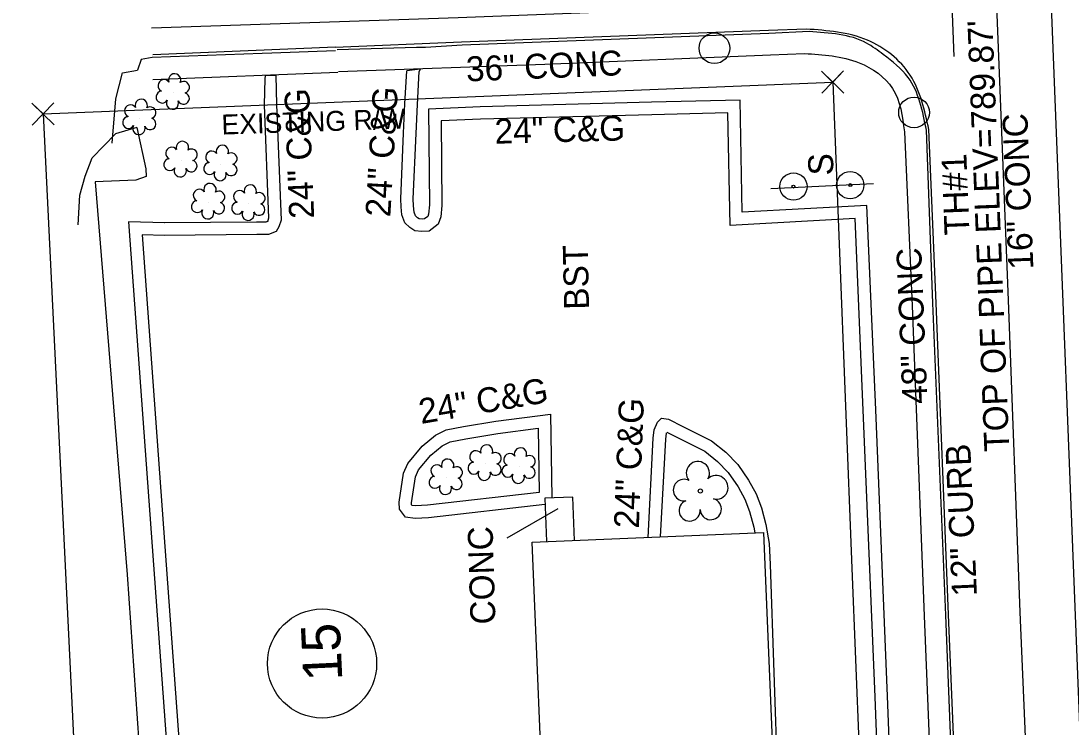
# Model space of a CAD drawing. Extents: x 1627482 to 1629573, y 760826 to 766301.
# Drawn here: x 1628266.8 to 1628435.1, y 762601.5 to 762714.8 of the extents above; entities that cross this region are included whole.
import ezdxf

# ---------------------------------------------------------------- set-up
doc = ezdxf.new("R2010")
doc.units = 0
for name, color, linetype in [('Default', 7, 'Continuous'), ('Exist Building', 7, 'Continuous'), ('Exist Horizontal Alignment', 7, 'Continuous'), ('Exist Other Culture Area Outline', 7, 'Continuous'), ('Exist Other Culture Area Outline Leader', 7, 'Continuous'), ('Exist Other Culture Area Outline Text', 7, 'Continuous'), ('Exist Other Culture Sign CELL', 7, 'Continuous'), ('Exist Other Culture Sign Post Text', 7, 'Continuous'), ('Exist Property Corner CELL', 7, 'Continuous'), ('Exist Property Line', 7, 'Continuous'), ('Exist Property Owner Number CELL', 7, 'Continuous'), ('Exist Right of Way Line', 7, 'Continuous'), ('Exist Right of Way Line Text', 7, 'Continuous'), ('Exist Roads Curbs', 7, 'Continuous'), ('Exist Roads Curbs Text', 7, 'Continuous'), ('Exist Roads EOP', 7, 'Continuous'), ('Exist Roads EOP Other', 7, 'Continuous'), ('Exist Roads EOP Other Text', 7, 'Continuous'), ('Exist Roads EOT', 7, 'Continuous'), ('Exist Utilities Other Pole CELL', 7, 'Continuous'), ('Exist Utilities Water Test Hole SUE LOS A Leader', 7, 'Continuous'), ('Exist Utilities Water Test Hole SUE LOS A Text', 7, 'Continuous'), ('Exist Vegetation Shrub CELL', 7, 'Continuous'), ('Exist Vegetation Tree CELL', 7, 'Continuous'), ('Exist Vegetation Woods Line', 7, 'Continuous')]:
    doc.layers.add(name, color=color, linetype=linetype)

# ---------------------------------------------------------------- blocks, each defined once
blk = doc.blocks.new('POINT_DISPLAY')
at = {"layer": 'Default'}
blk.add_line((0, 0), (0, 0), dxfattribs=at)
blk = doc.blocks.new('EXIST PROPERTY CORNER')
at = {"layer": 'Exist Property Corner CELL'}
blk.add_lwpolyline([(-3.81, 0), (3.81, 0), (0, 0), (0, 3.81), (0, -3.81)], dxfattribs=at)
blk.add_blockref('POINT_DISPLAY', (0, 0), dxfattribs=at)

msp = doc.modelspace()

# ---------------------------------------------------------------- linework, layer by layer
at = {"layer": 'Exist Building'}
msp.add_lwpolyline([(1628350.78, 762581.05), (1628348.7, 762631.18), (1628385.79, 762632.71), (1628387.44, 762592.91), (1628392, 762593.1), (1628392.29, 762586.01), (1628387.82, 762585.82), (1628387.93, 762582.98), (1628385.47, 762582.88), (1628386.67, 762554.01), (1628391.58, 762554.21), (1628391.79, 762548.97), (1628386.95, 762548.77), (1628387, 762547.42), (1628357.87, 762546.21), (1628356.42, 762581.29)], close=True, dxfattribs=at)
at = {"layer": 'Exist Horizontal Alignment'}
msp.add_line((1628461.18, 761975.88), (1628351.56, 764755.6), dxfattribs=at)
at = {"layer": 'Exist Other Culture Area Outline'}
msp.add_lwpolyline([(1628355.52, 762631.46), (1628355.24, 762638.41), (1628350.72, 762638.23), (1628350.99, 762631.27)], dxfattribs=at)
at = {"layer": 'Exist Other Culture Area Outline Leader'}
msp.add_line((1628352.81, 762636.51), (1628344.66, 762631.8), dxfattribs=at)
at = {"layer": 'Exist Other Culture Sign CELL'}
msp.add_line((1628403.45, 762688.65), (1628386.99, 762687.86), dxfattribs=at)
for centre, radius in [((1628390.59, 762688.21), 2.18), ((1628399.7, 762688.44), 2.18), ((1628390.59, 762688.21), 0.24), ((1628399.7, 762688.44), 0.24)]:
    msp.add_circle(centre, radius, dxfattribs=at)
at = {"layer": 'Exist Property Line'}
msp.add_line((1628270.32, 762699.87), (1628291.22, 762271.17), dxfattribs=at)
at = {"layer": 'Exist Property Owner Number CELL'}
msp.add_circle((1628315.04, 762611.71), 8.75, dxfattribs=at)
at = {"layer": 'Exist Right of Way Line'}
for p, q in [((1628270.32, 762699.87), (1628396.89, 762704.96)), ((1628396.89, 762704.96), (1628399.95, 762627.02)), ((1628270.28, 762699.87), (1628270.32, 762699.87)), ((1628399.95, 762627.02), (1628403.37, 762540.09))]:
    msp.add_line(p, q, dxfattribs=at)
at = {"layer": 'Exist Roads Curbs'}
for p, q in [((1628305.92, 762705.96), (1628305.88, 762705.51)), ((1628330.74, 762707.03), (1628330.62, 762706.69)), ((1628305.88, 762705.51), (1628305.75, 762701.3))]:
    msp.add_line(p, q, dxfattribs=at)
for points in [[(1628393.11, 762713.06), (1628386.65, 762712.77), (1628337.52, 762710.87), (1628331.61, 762710.54), (1628330.18, 762710.52), (1628317.47, 762710.16)], [(1628317.17, 762710.01), (1628307, 762709.6), (1628305.42, 762709.54), (1628287.82, 762708.9)], [(1628287.82, 762708.9), (1628286.05, 762708.6), (1628285.48, 762706.9)], [(1628367.86, 762701.73), (1628340.37, 762701.02), (1628332.12, 762700.64), (1628332.24, 762685.28), (1628332.11, 762683.79), (1628331.97, 762683.41), (1628331.46, 762683.03), (1628331.08, 762683), (1628330.6, 762683.05), (1628330.35, 762683.22), (1628330.02, 762683.53), (1628329.82, 762684.11), (1628329.71, 762685.11), (1628329.65, 762686.25), (1628330.11, 762696.71), (1628330.33, 762701.38), (1628330.62, 762706.69)], [(1628305.75, 762701.3), (1628306.48, 762683.12), (1628306.3, 762682.58), (1628306.34, 762682.64), (1628306.04, 762682.53), (1628304.55, 762682.5), (1628289.77, 762682.37)], [(1628407.42, 762561.04), (1628405.67, 762606.46), (1628403.79, 762652.41), (1628402.38, 762685.19), (1628382.39, 762684.09), (1628382.06, 762702.07), (1628367.86, 762701.73)], [(1628422.8, 762420.02), (1628422.73, 762422.65), (1628422.05, 762434.35), (1628421.99, 762438.03), (1628421.52, 762448.04), (1628421.28, 762459.31), (1628421.18, 762461.08), (1628420.69, 762471.21), (1628418.85, 762520.9), (1628416.94, 762570.65), (1628415.01, 762619.48), (1628412.94, 762669.51), (1628411.9, 762697.24)], [(1628289.86, 762682.37), (1628284.04, 762682.56), (1628291.45, 762580.61)], [(1628349.85, 762639.13), (1628331.92, 762637.1), (1628330.01, 762637.01), (1628329.49, 762637.07), (1628329.4, 762637.18), (1628329.39, 762637.49), (1628330.04, 762641.67), (1628330.52, 762642.76), (1628332.48, 762645.15), (1628334.31, 762646.65), (1628335.58, 762647.26), (1628338.06, 762647.74), (1628343.19, 762648.59), (1628349.67, 762649.44), (1628349.85, 762639.13)], [(1628369.31, 762632.03), (1628370.12, 762647.71), (1628370.23, 762648.68), (1628370.24, 762648.71)], [(1628370.29, 762648.81), (1628372, 762647.95), (1628376.39, 762645.75), (1628378.43, 762644.13), (1628380.12, 762642.35), (1628381.71, 762640.06), (1628382.82, 762638.07), (1628383.57, 762636.09), (1628384.22, 762633.59), (1628384.38, 762632.66)]]:
    msp.add_lwpolyline(points, dxfattribs=at)
msp.add_spline([(1628411.9, 762697.24), (1628408.97, 762705.72), (1628404.99, 762709.4), (1628402.32, 762711.22), (1628393.11, 762713.06)], degree=3, dxfattribs=at)
at = {"layer": 'Exist Roads EOP'}
for p, q in [((1628287.91, 762709.41), (1628317.21, 762710.64)), ((1628283.07, 762706.48), (1628285.48, 762706.9))]:
    msp.add_line(p, q, dxfattribs=at)
for points in [[(1628392.64, 762713.47), (1628386.59, 762713.27), (1628337.41, 762711.39), (1628317.16, 762710.54)], [(1628281.42, 762695.2), (1628281.98, 762702.31), (1628283.07, 762706.48)], [(1628423.26, 762422.73), (1628421.92, 762448.14), (1628421.59, 762459.48), (1628421.23, 762471.28), (1628419.31, 762520.97), (1628417.49, 762570.66), (1628415.44, 762619.55), (1628413.46, 762669.52), (1628412.29, 762697.36)]]:
    msp.add_lwpolyline(points, dxfattribs=at)
msp.add_spline([(1628412.29, 762697.36), (1628409.31, 762706.06), (1628402.45, 762711.7), (1628392.64, 762713.47)], degree=3, dxfattribs=at)
at = {"layer": 'Exist Roads EOP Other'}
for p, q in [((1628287.9, 762705.36), (1628317.57, 762706.56)), ((1628307.61, 762706.01), (1628305.92, 762705.96)), ((1628307.61, 762706.01), (1628307.75, 762701.38)), ((1628330.74, 762707.03), (1628328.62, 762706.8))]:
    msp.add_line(p, q, dxfattribs=at)
for points in [[(1628317.7, 762706.65), (1628350.74, 762707.86), (1628386.89, 762709.34), (1628392.37, 762709.56)], [(1628367.91, 762699.73), (1628340.44, 762699.02), (1628334.13, 762698.73), (1628334.24, 762685.2), (1628334.08, 762683.35), (1628333.64, 762682.17), (1628332.2, 762681.08), (1628331.05, 762680.99), (1628329.9, 762681.12), (1628329.1, 762681.64), (1628328.3, 762682.41), (1628327.85, 762683.66), (1628327.71, 762684.96), (1628327.65, 762686.25), (1628328.11, 762696.8), (1628328.33, 762701.48), (1628328.62, 762706.8)], [(1628307.75, 762701.38), (1628308.49, 762682.84), (1628308.12, 762681.73), (1628307.68, 762681.01), (1628306.43, 762680.54), (1628304.58, 762680.5), (1628289.79, 762680.37)], [(1628405.42, 762560.96), (1628403.67, 762606.38), (1628401.79, 762652.33), (1628400.47, 762683.08), (1628380.43, 762681.98), (1628380.09, 762700.02), (1628367.91, 762699.73)], [(1628408.37, 762697), (1628409.62, 762669.07), (1628411.56, 762619.37), (1628413.5, 762570.37), (1628415.53, 762520.63), (1628417.53, 762471), (1628417.53, 762457.85), (1628418.62, 762435.24), (1628419.13, 762428.56), (1628419.53, 762425.05), (1628422.64, 762422.63)], [(1628289.79, 762680.37), (1628286.19, 762680.49), (1628293.47, 762580.49)], [(1628350.76, 762637.22), (1628332.08, 762635.1), (1628329.94, 762635), (1628328.43, 762635.17), (1628327.43, 762636.45), (1628327.38, 762637.6), (1628328.1, 762642.24), (1628328.8, 762643.81), (1628331.06, 762646.57), (1628333.23, 762648.35), (1628334.94, 762649.18), (1628337.71, 762649.71), (1628342.9, 762650.57), (1628351.63, 762651.72), (1628351.86, 762638.28)], [(1628367.3, 762631.95), (1628368.12, 762647.87), (1628368.28, 762649.2), (1628368.8, 762650.43), (1628369.44, 762651.07), (1628370.59, 762650.9), (1628372.89, 762649.73), (1628377.47, 762647.45), (1628379.78, 762645.61), (1628381.68, 762643.61), (1628383.41, 762641.12), (1628384.63, 762638.92), (1628385.48, 762636.7), (1628386.17, 762634.01), (1628386.71, 762630.97), (1628386.84, 762627.59)], [(1628386.84, 762627.59), (1628388.06, 762592.94)]]:
    msp.add_lwpolyline(points, dxfattribs=at)
msp.add_spline([(1628392.37, 762709.56), (1628401.12, 762708.07), (1628406.48, 762703.94), (1628408.37, 762697)], degree=3, dxfattribs=at)
at = {"layer": 'Exist Roads EOT'}
for points in [[(1628434.97, 762422.94), (1628433.98, 762450.35), (1628433.05, 762472.58), (1628431.01, 762521.44), (1628429.03, 762571.24), (1628426.95, 762619.94), (1628425.07, 762669.97), (1628423.08, 762719.91), (1628421.14, 762768.33), (1628419.22, 762818.47), (1628417.26, 762867.57), (1628415.36, 762916.71), (1628413.28, 762965.8), (1628411.46, 763014.64), (1628409.29, 763063.34), (1628407.41, 763114.2), (1628406.34, 763142.28)], [(1628396.18, 762717.52), (1628385.6, 762717.13), (1628336.83, 762715.26), (1628287.7, 762713.6)]]:
    msp.add_lwpolyline(points, dxfattribs=at)
at = {"layer": 'Exist Utilities Other Pole CELL'}
for centre in [(1628377.92, 762710.4), (1628409.92, 762700.1)]:
    msp.add_circle(centre, 2.46, dxfattribs=at)
at = {"layer": 'Exist Utilities Water Test Hole SUE LOS A Leader'}
msp.add_lwpolyline([(1628421.84, 762740.13), (1628415.22, 762736.6), (1628416.31, 762709.06)], dxfattribs=at)
at = {"layer": 'Exist Vegetation Shrub CELL'}
for p, q in [((1628291.19, 762703.28), (1628291.19, 762703.28)), ((1628285.83, 762699.2), (1628285.83, 762699.2)), ((1628292.43, 762692.44), (1628292.43, 762692.44)), ((1628298.83, 762691.82), (1628298.83, 762691.82)), ((1628296.85, 762685.69), (1628296.85, 762685.69)), ((1628303.3, 762685.46), (1628303.3, 762685.46)), ((1628341.18, 762643.76), (1628341.18, 762643.76)), ((1628346.61, 762643.28), (1628346.61, 762643.28)), ((1628334.94, 762641.48), (1628334.94, 762641.48))]:
    msp.add_line(p, q, dxfattribs=at)
for centre, radius, start, end in [((1628291.42, 762705.32), 0.99, 334.8391, 200.4717), ((1628289.71, 762704.4), 0.968, 35.8908, 245.4216), ((1628292.86, 762704.14), 0.929, 284.4567, 126.0861), ((1628289.39, 762702.57), 0.955, 95.1099, 327.9534), ((1628292.83, 762702.35), 0.937, 204.9913, 73.4601), ((1628284.35, 762700.33), 0.968, 35.8908, 245.4216), ((1628286.06, 762701.24), 0.99, 334.8391, 200.4717), ((1628287.5, 762700.07), 0.929, 284.4567, 126.0861), ((1628291.06, 762701.59), 0.984, 151.2797, 21.387), ((1628284.03, 762698.49), 0.955, 95.1099, 327.9534), ((1628287.47, 762698.27), 0.937, 204.9913, 73.4601), ((1628285.7, 762697.52), 0.984, 151.2797, 21.387), ((1628290.95, 762693.56), 0.968, 35.8908, 245.4216), ((1628292.66, 762694.48), 0.99, 334.8391, 200.4717), ((1628294.11, 762693.31), 0.929, 284.4567, 126.0861), ((1628299.06, 762693.86), 0.99, 334.8391, 200.4717), ((1628290.63, 762691.73), 0.955, 95.1099, 327.9534), ((1628297.35, 762692.94), 0.968, 35.8908, 245.4216), ((1628300.5, 762692.69), 0.929, 284.4567, 126.0861), ((1628292.31, 762690.75), 0.984, 151.2797, 21.387), ((1628294.07, 762691.51), 0.937, 204.9913, 73.4601), ((1628297.03, 762691.11), 0.955, 95.1099, 327.9534), ((1628300.47, 762690.89), 0.937, 204.9913, 73.4601), ((1628298.7, 762690.13), 0.984, 151.2797, 21.387), ((1628295.37, 762686.82), 0.968, 35.8908, 245.4216), ((1628297.08, 762687.73), 0.99, 334.8391, 200.4717), ((1628298.52, 762686.56), 0.929, 284.4567, 126.0861), ((1628301.82, 762686.59), 0.968, 35.8908, 245.4216), ((1628303.53, 762687.5), 0.99, 334.8391, 200.4717), ((1628295.05, 762684.99), 0.955, 95.1099, 327.9534), ((1628301.5, 762684.75), 0.955, 95.1099, 327.9534), ((1628304.98, 762686.33), 0.929, 284.4567, 126.0861), ((1628296.72, 762684.01), 0.984, 151.2797, 21.387), ((1628298.49, 762684.76), 0.937, 204.9913, 73.4601), ((1628303.18, 762683.77), 0.984, 151.2797, 21.387), ((1628304.94, 762684.53), 0.937, 204.9913, 73.4601), ((1628339.69, 762644.88), 0.968, 35.8908, 245.4216), ((1628341.41, 762645.8), 0.99, 334.8391, 200.4717), ((1628342.85, 762644.63), 0.929, 284.4567, 126.0861), ((1628345.13, 762644.41), 0.968, 35.8908, 245.4216), ((1628346.84, 762645.32), 0.99, 334.8391, 200.4717), ((1628335.17, 762643.52), 0.99, 334.8391, 200.4717), ((1628339.38, 762643.05), 0.955, 95.1099, 327.9534), ((1628342.81, 762642.83), 0.937, 204.9913, 73.4601), ((1628348.29, 762644.15), 0.929, 284.4567, 126.0861), ((1628333.45, 762642.61), 0.968, 35.8908, 245.4216), ((1628336.61, 762642.35), 0.929, 284.4567, 126.0861), ((1628341.05, 762642.07), 0.984, 151.2797, 21.387), ((1628344.81, 762642.57), 0.955, 95.1099, 327.9534), ((1628346.49, 762641.59), 0.984, 151.2797, 21.387), ((1628348.25, 762642.35), 0.937, 204.9913, 73.4601), ((1628333.14, 762640.78), 0.955, 95.1099, 327.9534), ((1628334.81, 762639.8), 0.984, 151.2797, 21.387), ((1628336.57, 762640.55), 0.937, 204.9913, 73.4601)]:
    msp.add_arc(centre, radius, start, end, dxfattribs=at)
at = {"layer": 'Exist Vegetation Tree CELL'}
msp.add_line((1628375.67, 762639.38), (1628375.67, 762639.38), dxfattribs=at)
msp.add_circle((1628375.67, 762639.38), 0.326, dxfattribs=at)
for centre, radius, start, end in [((1628375.28, 762642.25), 1.86, 330.1651, 219.7134), ((1628373.06, 762639.53), 1.73, 62.6636, 279.3457), ((1628378.21, 762639.96), 1.9, 257.1011, 134.1999), ((1628373.96, 762636.25), 1.69, 111.5671, 6.231), ((1628377.34, 762636.48), 1.7, 181.2822, 74.56)]:
    msp.add_arc(centre, radius, start, end, dxfattribs=at)
at = {"layer": 'Exist Vegetation Woods Line'}
msp.add_line((1628285.33, 762697.69), (1628281.93, 762696.68), dxfattribs=at)
for points in [[(1628285.33, 762697.69), (1628286.77, 762691.06), (1628286.83, 762689.85), (1628285.21, 762689.25), (1628278.68, 762688.95), (1628283.78, 762625.98), (1628287.01, 762579.8), (1628289.6, 762525.9), (1628292.05, 762459.1), (1628292.94, 762439.75)], [(1628275.94, 762682.07), (1628276.22, 762686.85), (1628277.08, 762689.9), (1628278.2, 762692.83), (1628281.93, 762696.68)]]:
    msp.add_lwpolyline(points, dxfattribs=at)

# ---------------------------------------------------------------- block references
at = {"layer": 'Exist Property Corner CELL', "xscale": 0.6561666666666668, "yscale": 0.6561666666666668, "rotation": 45.72460018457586}
for p in [(1628396.89, 762704.96), (1628270.32, 762699.87)]:
    msp.add_blockref('EXIST PROPERTY CORNER', p, dxfattribs=at)

# ---------------------------------------------------------------- texts
at = {"layer": 'Exist Other Culture Area Outline Text'}
msp.add_text('CONC', height=4, rotation=91.7713, dxfattribs=at).set_placement((1628342.85, 762618.04))
at = {"layer": 'Exist Other Culture Sign Post Text'}
msp.add_text('S', height=4, rotation=90, dxfattribs=at).set_placement((1628396.97, 762689.99))
at = {"layer": 'Exist Property Owner Number CELL'}
msp.add_text('15', height=6.25, rotation=92.6915, dxfattribs=at).set_placement((1628318.3, 762609.05))
at = {"layer": 'Exist Right of Way Line Text'}
msp.add_text('EXISTING R/W', height=3.2, rotation=1.8804, dxfattribs=at).set_placement((1628298.97, 762696.55))
at = {"layer": 'Exist Roads Curbs Text'}
for s, rotation, p in [('24" C&G', 92.204, (1628313.78, 762683.13)), ('24" C&G', 86.6133, (1628325.97, 762683.25)), ('24" C&G', 1.4726, (1628342.74, 762695.08)), ('24" C&G', 9.7516, (1628330.91, 762650.13)), ('24" C&G', 87.7263, (1628365.81, 762633.33)), ('12" CURB', 92.5309, (1628420.01, 762622.57))]:
    msp.add_text(s, height=4, rotation=rotation, dxfattribs=at).set_placement(p)
at = {"layer": 'Exist Roads EOP Other Text'}
for s, rotation, p in [('36" CONC', 2.3406, (1628338.19, 762705.06)), ('BST', 91.2932, (1628357.85, 762668.5)), ('48" CONC', 92.3406, (1628412.09, 762653.43))]:
    msp.add_text(s, height=4, rotation=rotation, dxfattribs=at).set_placement(p)
at = {"layer": 'Exist Utilities Water Test Hole SUE LOS A Text'}
for s, p in [("TOP OF PIPE ELEV=789.87'", (1628425.2, 762645.77)), ('16" CONC', (1628429.06, 762674.98)), ('TH#1', (1628418.82, 762680.5))]:
    msp.add_text(s, height=4, rotation=92.2582, dxfattribs=at).set_placement(p)

doc.saveas('drawing.dxf')
